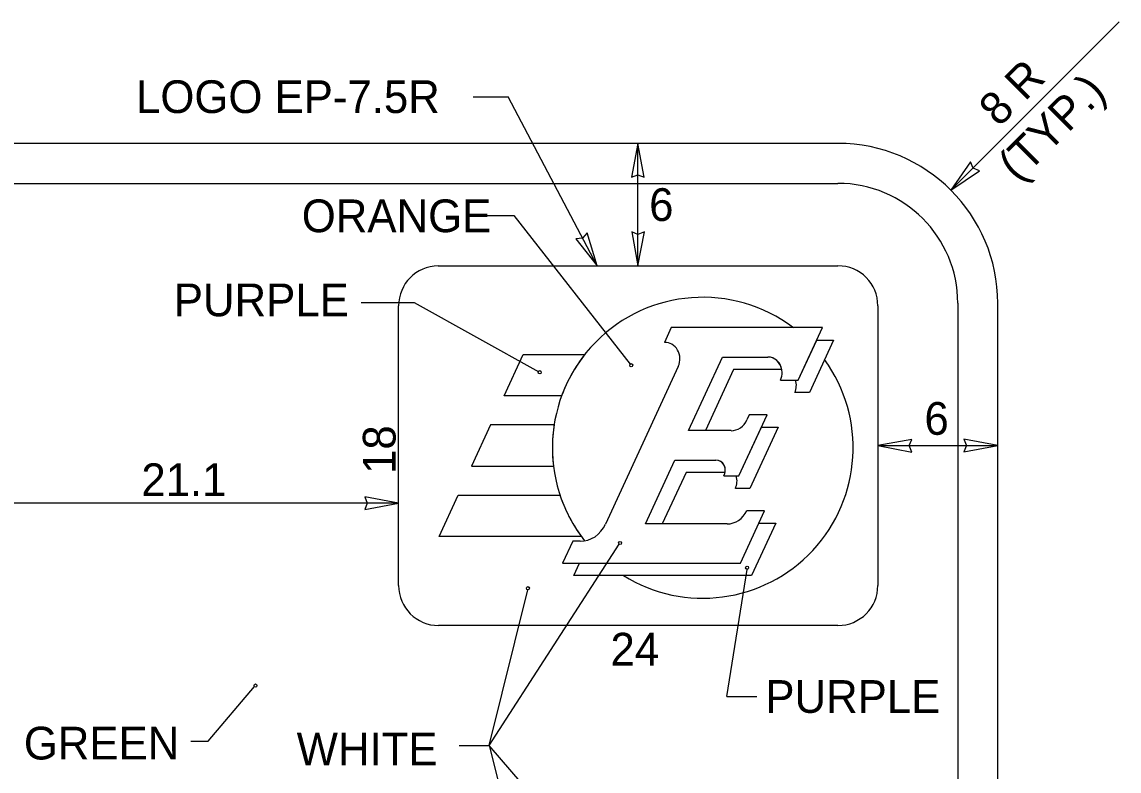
# Model space of a CAD drawing. Extents: x 319706 to 320449, y 1621775 to 1622117.
# Drawn here: x 320236.54 to 320283.51, y 1621875.55 to 1621907.6 of the extents above; entities that cross this region are included whole.
import ezdxf

# ---------------------------------------------------------------- set-up
doc = ezdxf.new("R2010")
doc.units = 0
for name, color, linetype in [('1', 7, 'Continuous'), ('52', 7, 'Continuous'), ('SignPanel', 7, 'Continuous')]:
    doc.layers.add(name, color=color, linetype=linetype)

msp = doc.modelspace()

# ---------------------------------------------------------------- linework, layer by layer
at = {"layer": '1'}
for p, q in [((320283.507, 1621907.6), (320276.309, 1621900.402)), ((320255.855, 1621904.403), (320257.352, 1621904.403)), ((320261.163, 1621897.166), (320257.352, 1621904.403)), ((320262.911, 1621897.166), (320262.911, 1621902.405)), ((320256.441, 1621899.321), (320257.589, 1621899.321)), ((320257.589, 1621899.321), (320262.572, 1621892.959)), ((320251.059, 1621895.595), (320253.334, 1621895.595)), ((320253.334, 1621895.595), (320258.669, 1621892.637)), ((320273.182, 1621889.471), (320278.312, 1621889.471)), ((320256.542, 1621876.645), (320262.1, 1621885.258)), ((320266.721, 1621878.739), (320267.581, 1621884.175)), ((320256.542, 1621876.645), (320258.197, 1621883.299)), ((320244.508, 1621876.825), (320246.488, 1621879.16)), ((320266.721, 1621878.739), (320268.004, 1621878.739)), ((320243.771, 1621876.825), (320244.508, 1621876.825)), ((320255.259, 1621876.645), (320256.542, 1621876.645)), ((320256.542, 1621876.645), (320258.197, 1621869.995)), ((320264.062, 1621867.926), (320256.542, 1621876.645))]:
    msp.add_line(p, q, dxfattribs=at)
for centre in [(320258.702, 1621892.611), (320262.619, 1621892.909), (320262.147, 1621885.307), (320267.581, 1621884.246), (320258.197, 1621883.369), (320246.535, 1621879.209)]:
    msp.add_ellipse(centre, major_axis=(0, 0.0707), ratio=0.906668, dxfattribs=at)
at = {"layer": '52'}
for p, q in [((320262.911, 1621902.405), (320262.631, 1621900.955)), ((320263.181, 1621900.955), (320262.911, 1621902.405)), ((320277.143, 1621901.618), (320276.309, 1621900.402)), ((320277.256, 1621901.349), (320277.143, 1621901.618)), ((320276.309, 1621900.402), (320277.532, 1621901.229)), ((320277.532, 1621901.229), (320277.256, 1621901.349)), ((320262.631, 1621900.955), (320262.911, 1621901.065)), ((320262.911, 1621901.065), (320263.181, 1621900.955)), ((320260.539, 1621898.351), (320260.248, 1621898.323)), ((320260.248, 1621898.323), (320261.163, 1621897.166)), ((320260.735, 1621898.579), (320260.539, 1621898.351)), ((320261.163, 1621897.166), (320260.735, 1621898.579)), ((320262.911, 1621898.506), (320262.641, 1621898.616)), ((320262.641, 1621898.616), (320262.911, 1621897.166)), ((320262.911, 1621897.166), (320263.191, 1621898.616)), ((320263.191, 1621898.616), (320262.911, 1621898.506)), ((320274.632, 1621889.741), (320273.182, 1621889.471)), ((320273.182, 1621889.471), (320274.632, 1621889.191)), ((320274.522, 1621889.471), (320274.632, 1621889.741)), ((320274.632, 1621889.191), (320274.522, 1621889.471)), ((320278.312, 1621889.471), (320276.862, 1621889.751)), ((320276.862, 1621889.751), (320276.972, 1621889.471)), ((320276.972, 1621889.471), (320276.862, 1621889.201)), ((320276.862, 1621889.201), (320278.312, 1621889.471)), ((320252.662, 1621887.004), (320251.212, 1621887.284)), ((320251.212, 1621887.284), (320251.322, 1621887.004)), ((320251.322, 1621887.004), (320251.212, 1621886.734)), ((320251.212, 1621886.734), (320252.662, 1621887.004))]:
    msp.add_line(p, q, dxfattribs=at)
at = {"layer": 'SignPanel'}
for p, q in [((320271.472, 1621902.405), (320162.031, 1621902.405)), ((320162.031, 1621900.695), (320271.472, 1621900.695)), ((320254.352, 1621897.166), (320271.471, 1621897.166)), ((320276.602, 1621895.565), (320276.602, 1621857.945)), ((320278.312, 1621857.945), (320278.312, 1621895.565)), ((320252.662, 1621883.486), (320252.662, 1621895.457)), ((320273.182, 1621895.457), (320273.182, 1621883.486)), ((320264.336, 1621894.52), (320264.048, 1621893.892)), ((320270.81, 1621894.52), (320264.336, 1621894.52)), ((320269.772, 1621892.277), (320270.81, 1621894.52)), ((320269.772, 1621892.277), (320270.566, 1621893.991)), ((320271.283, 1621893.991), (320270.248, 1621891.746)), ((320270.566, 1621893.991), (320271.283, 1621893.991)), ((320257.177, 1621891.604), (320257.992, 1621893.372)), ((320257.992, 1621893.372), (320260.633, 1621893.372)), ((320265.077, 1621890.113), (320266.531, 1621893.262)), ((320265.077, 1621890.113), (320266.531, 1621893.262)), ((320266.531, 1621893.262), (320268.472, 1621893.262)), ((320266.531, 1621893.262), (320268.472, 1621893.262)), ((320264.638, 1621892.862), (320261.52, 1621886.114)), ((320267.006, 1621892.732), (320265.795, 1621890.113)), ((320269.067, 1621892.732), (320267.006, 1621892.732)), ((320269.012, 1621892.277), (320269.772, 1621892.277)), ((320269.659, 1621892.277), (320269.772, 1621892.277)), ((320270.248, 1621891.746), (320269.622, 1621891.746)), ((320259.642, 1621891.604), (320257.177, 1621891.604)), ((320259.642, 1621891.604), (320259.642, 1621891.604)), ((320267.232, 1621888.174), (320268.44, 1621890.793)), ((320267.677, 1621890.793), (320267.577, 1621890.57)), ((320268.44, 1621890.793), (320267.677, 1621890.793)), ((320256.603, 1621890.365), (320255.787, 1621888.598)), ((320259.322, 1621890.365), (320256.603, 1621890.365)), ((320266.899, 1621890.113), (320265.077, 1621890.113)), ((320265.795, 1621890.113), (320265.077, 1621890.113)), ((320267.232, 1621888.174), (320268.194, 1621890.261)), ((320268.916, 1621890.261), (320267.705, 1621887.642)), ((320268.196, 1621890.261), (320268.916, 1621890.261)), ((320255.787, 1621888.598), (320259.292, 1621888.598)), ((320263.233, 1621886.122), (320264.495, 1621888.854)), ((320263.233, 1621886.122), (320264.495, 1621888.854)), ((320264.495, 1621888.854), (320266.25, 1621888.854)), ((320264.495, 1621888.854), (320266.25, 1621888.854)), ((320264.969, 1621888.322), (320263.952, 1621886.122)), ((320266.644, 1621888.322), (320264.969, 1621888.322)), ((320266.586, 1621888.174), (320267.232, 1621888.174)), ((320267.117, 1621888.174), (320267.232, 1621888.174)), ((320267.705, 1621887.642), (320267.08, 1621887.642)), ((320254.399, 1621885.591), (320255.215, 1621887.359)), ((320255.215, 1621887.359), (320259.572, 1621887.359)), ((320252.662, 1621887.004), (320234.621, 1621887.004)), ((320267.297, 1621884.445), (320268.334, 1621886.688)), ((320268.334, 1621886.688), (320267.571, 1621886.688)), ((320266.728, 1621886.122), (320263.233, 1621886.122)), ((320263.952, 1621886.122), (320263.233, 1621886.122)), ((320266.727, 1621886.124), (320266.728, 1621886.122)), ((320267.297, 1621884.445), (320268.089, 1621886.158)), ((320268.808, 1621886.158), (320267.771, 1621883.913)), ((320268.089, 1621886.158), (320268.808, 1621886.158)), ((320260.479, 1621885.591), (320254.399, 1621885.591)), ((320260.116, 1621885.378), (320259.682, 1621884.445)), ((320260.435, 1621885.378), (320260.116, 1621885.378)), ((320259.682, 1621884.445), (320267.297, 1621884.445)), ((320260.158, 1621883.913), (320260.402, 1621884.445)), ((320260.402, 1621884.445), (320267.297, 1621884.445)), ((320267.771, 1621883.913), (320260.158, 1621883.913)), ((320271.471, 1621881.777), (320254.373, 1621881.777))]:
    msp.add_line(p, q, dxfattribs=at)
for centre, radius, start, end in [((320271.472, 1621895.565), 6.84, 0, 90), ((320271.472, 1621895.565), 5.13, 0, 90), ((320254.372, 1621895.456), 1.71, 90.6597, 180), ((320271.471, 1621895.456), 1.71, 0, 90), ((320265.684, 1621889.381), 6.438, 52.9575, 218.2327), ((320265.684, 1621889.381), 6.438, 141.6926, 159.8015), ((320265.684, 1621889.381), 6.438, 238.1326, 35.91), ((320265.684, 1621889.381), 6.438, 171.2075, 186.983), ((320265.684, 1621889.381), 6.438, 198.3, 216.0576), ((320254.372, 1621883.487), 1.71, 180, 270), ((320271.471, 1621883.487), 1.71, 270, 360)]:
    msp.add_arc(centre, radius, start, end, dxfattribs=at)
for centre, major_axis, start_param, end_param in [((320264.066, 1621893.184), (0, 0.707), 4.241328, 6.314398), ((320268.472, 1621892.59), (0, 0.672), 4.227342, 6.283185), ((320268.472, 1621892.59), (0, 0.672), 4.924621, 6.283185), ((320269.082, 1621892.06), (0, 0.672), 4.227342, 5.041732), ((320266.898, 1621890.952), (0, 0.84), 3.141593, 4.241405), ((320266.249, 1621888.411), (0, 0.442), 4.144801, 6.283185), ((320266.249, 1621888.411), (0, 0.442), 4.51088, 6.283185), ((320266.541, 1621887.956), (0, 0.672), 4.227342, 5.041732), ((320266.727, 1621887.173), (0, 1.05), 3.141593, 4.232591), ((320260.434, 1621886.723), (0, 1.344), 3.141593, 4.241135)]:
    msp.add_ellipse(centre, major_axis=major_axis, ratio=0.906668, start_param=start_param, end_param=end_param, dxfattribs=at)

# ---------------------------------------------------------------- texts
at = {"layer": '1'}
for s, rotation, p in [('8 R', 45, (320278.37, 1621903.068)), ('(TYP.)', 45, (320279.19, 1621900.698)), ('18', 90, (320252.532, 1621888.26))]:
    msp.add_text(s, height=1.4, rotation=rotation, dxfattribs=at).set_placement(p)
for s, p in [('LOGO EP-7.5R', (320241.421, 1621903.703)), ('6', (320263.389, 1621899.085)), ('ORANGE', (320248.516, 1621898.605)), ('PURPLE', (320243.038, 1621895.007)), ('6', (320275.175, 1621889.936)), ('21.1', (320241.648, 1621887.315)), ('24', (320261.734, 1621880.064)), ('PURPLE', (320268.364, 1621878.039)), ('GREEN', (320236.616, 1621876.044)), ('WHITE', (320248.297, 1621875.789))]:
    msp.add_text(s, height=1.4, dxfattribs=at).set_placement(p)

doc.saveas('drawing.dxf')
